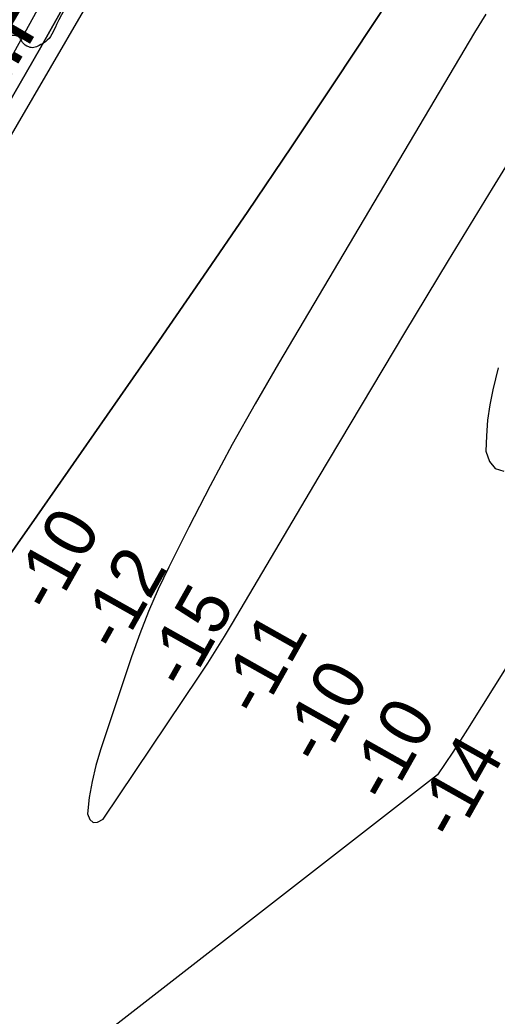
# Model space of a CAD drawing. Extents: x 3297735 to 3335592, y 670436 to 695807.
# Drawn here: x 3318736 to 3319354, y 691316 to 692609 of the extents above; entities that cross this region are included whole.
import ezdxf

# ---------------------------------------------------------------- set-up
doc = ezdxf.new("R2010")
doc.units = 0
for name, color, linetype in [('V-RIVR-EDGE', 7, 'Continuous'), ('V-RIVR-RANG', 7, 'Continuous'), ('V-TOPO-DPTH', 7, 'Continuous'), ('V-TOPO-MINR', 7, 'Continuous'), ('V-TOPO-WATR', 7, 'Continuous'), ('V-TOPO-WATR-IDEN', 7, 'Continuous')]:
    doc.layers.add(name, color=color, linetype=linetype)

msp = doc.modelspace()

# ---------------------------------------------------------------- linework, layer by layer
at = {"layer": 'V-RIVR-EDGE'}
msp.add_spline([(3319555.1, 694014.6), (3319548.5, 694002.8), (3319539.4, 693985.8), (3319509.8, 693923.3), (3319496.5, 693903), (3319479.4, 693878.2), (3319464, 693854.6), (3319445.3, 693819), (3319424.4, 693775.5), (3319406.5, 693740.7), (3319395.7, 693713), (3319386.5, 693693.1), (3319372.8, 693671.6), (3319340.3, 693621.5), (3319316.6, 693580.1), (3319295.8, 693542.9), (3319282.1, 693521), (3319271.7, 693502.3), (3319267.9, 693489.5), (3319260, 693475.8), (3319250.4, 693465.1), (3319246.2, 693454.3), (3319237.9, 693442.3), (3319231.7, 693428.7), (3319225.4, 693415), (3319219.6, 693410), (3319205.5, 693391.4), (3319185.1, 693363.3), (3319164.7, 693327.7), (3319143.1, 693301.2), (3319109.4, 693253.2), (3319083.6, 693218.5), (3319061.1, 693187.8), (3319039.5, 693157.6), (3319018.3, 693123.3), (3318994.6, 693091), (3318949.7, 693031.9), (3318931.4, 693004.6), (3318913.1, 692981.4), (3318902.3, 692962.8), (3318892.7, 692944.5), (3318876, 692916.4), (3318861.9, 692887.8), (3318841.5, 692848.5), (3318822.3, 692807.5), (3318806.5, 692774.4), (3318803.1, 692758.7), (3318804.3, 692745), (3318808, 692734.6), (3318808.8, 692730.5), (3318817.1, 692725.5), (3318826.6, 692719.2), (3318832.8, 692713), (3318835.7, 692705.5), (3318835.3, 692692.3), (3318829.9, 692681.5), (3318819.9, 692669.1), (3318809.5, 692651.3), (3318783.2, 692602.9), (3318768.7, 692580.5), (3318760.8, 692576), (3318753.7, 692573.1), (3318747.1, 692573.9), (3318739.2, 692579.8), (3318735.5, 692585.6), (3318730.6, 692588.5), (3318721.4, 692588.1), (3318700.3, 692573.6), (3318679.5, 692549.7), (3318660.8, 692522.3), (3318646.6, 692493.4), (3318637, 692477.6), (3318625, 692456.9), (3318607.1, 692434.2), (3318600, 692413.5), (3318583.3, 692372.5), (3318565.8, 692342.3), (3318547.1, 692313.7), (3318534.2, 692295.5), (3318512.6, 692258.7), (3318488, 692224.8), (3318446.4, 692155.2), (3318418.1, 692112.6), (3318397.3, 692084.5), (3318386.9, 692066.7), (3318376.5, 692048), (3318354.4, 692011.2), (3318333.2, 691976.5), (3318316.1, 691940), (3318301.6, 691917.7), (3318275.4, 691885), (3318265.8, 691873), (3318250.8, 691844.8), (3318236.6, 691808.4), (3318222.1, 691781.1), (3318195, 691714), (3318180, 691684.2), (3318162.1, 691654.8), (3318140.8, 691619.6), (3318130.4, 691603.9), (3318120.9, 691595.2), (3318105.1, 691577.9), (3318090.1, 691558.4), (3318067.7, 691532.4), (3318043.6, 691501.8), (3318020.3, 691465.8), (3317998.2, 691433.1), (3317973.7, 691392.9), (3317962.4, 691371.8), (3317929.9, 691315.1), (3317907.9, 691282.4), (3317889.2, 691263.4), (3317870.5, 691238.2), (3317844.7, 691203), (3317833.1, 691186), (3317808.1, 691148.8), (3317780.6, 691109.5), (3317756.1, 691076.4), (3317732, 691045.3), (3317684.6, 690978.7), (3317668.8, 690954.7), (3317646.3, 690922), (3317635.5, 690907.1), (3317629.2, 690900.5), (3317620.1, 690889.4), (3317608.5, 690874.5), (3317601.4, 690867), (3317592.7, 690860.4), (3317585.6, 690845.9), (3317576.9, 690836), (3317565.6, 690821.1), (3317549.4, 690801.3), (3317522.4, 690767.7), (3317502.4, 690745), (3317490, 690727.6), (3317482.5, 690713.5), (3317479.5, 690701.1), (3317475.8, 690689.9), (3317474.9, 690683.3), (3317467.9, 690674.2), (3317451.7, 690653.9), (3317427.5, 690622.9), (3317406.3, 690594), (3317381.8, 690564.6), (3317328.2, 690504.6), (3317308.2, 690483.1), (3317290.8, 690466.2), (3317272.5, 690446.3), (3317248.8, 690422.7), (3317230.9, 690402.5), (3317202.2, 690356.5), (3317170.2, 690314.3), (3317129.5, 690266.4), (3317099.1, 690227.5), (3317085.8, 690212.6), (3317074.2, 690204.3), (3317063.4, 690189.8), (3317045.1, 690163.8), (3317020.9, 690128.6), (3316996.8, 690093.9), (3316970.6, 690059.1), (3316927, 690008.2), (3316891.7, 689970.6), (3316861.7, 689930.1), (3316828, 689887.9), (3316809.3, 689860.1), (3316797.2, 689841.9), (3316783.5, 689825.4), (3316737.4, 689762.1), (3316714.9, 689729), (3316681.6, 689687.6), (3316661.7, 689665.7), (3316648, 689646.7), (3316619.7, 689606.1), (3316602.6, 689581.3), (3316583.5, 689551.9), (3316563.9, 689519.6), (3316547.7, 689499.3), (3316541.9, 689491.9), (3316538.6, 689488.6), (3316532.3, 689474.1), (3316523.2, 689461.3), (3316509, 689445.1), (3316500.3, 689431.5), (3316493.2, 689419.9), (3316485.7, 689407.9), (3316486.1, 689397.1), (3316486.5, 689375.6), (3316487.3, 689371), (3316491.4, 689370.2), (3316493.5, 689366.4), (3316494.3, 689352.8), (3316496.8, 689341.6), (3316502.5, 689336.6), (3316504.2, 689334.1), (3316504.2, 689328.7), (3316501.3, 689325.8), (3316488.8, 689321.3), (3316487.2, 689319.6), (3316487.2, 689316.7), (3316493, 689316.7), (3316502.1, 689318.3), (3316508.3, 689318.3), (3316513.3, 689315), (3316516.6, 689315), (3316524.9, 689314.5), (3316535.6, 689303.3), (3316544.7, 689293.4), (3316545.5, 689290), (3316543.5, 689288), (3316525.7, 689296.7), (3316509.9, 689304.2), (3316502.1, 689307.1), (3316490.5, 689308.4), (3316482.6, 689308), (3316478, 689308), (3316473.5, 689311.8), (3316449.5, 689323.9), (3316424.6, 689324.7), (3316401.8, 689323.1), (3316381.5, 689318.2), (3316366.5, 689316.2), (3316352.9, 689311.2), (3316334.2, 689295.5), (3316302.2, 689277.8), (3316275.2, 689257.1), (3316266.5, 689249.3), (3316249, 689224), (3316230.3, 689191.8), (3316217.8, 689162.8), (3316200.7, 689125.9), (3316182.4, 689092.8), (3316162.8, 689054.7), (3316141.2, 689024.9), (3316114.6, 688996.4), (3316081.8, 688971.6), (3316036.9, 688926.1), (3316007.4, 688897.6), (3315987, 688880.7), (3315970, 688865.8), (3315959.6, 688858.8), (3315957.1, 688852.1), (3315955.5, 688848.4), (3315953.9, 688835.5)], degree=3, dxfattribs=at)
at = {"layer": 'V-TOPO-DPTH'}
for points in [[(3318722.4, 691914.9), (3318736.6, 691934.9), (3318750.7, 691954.9), (3318764.7, 691975), (3318916.3, 692193.1), (3318973.8, 692276.6), (3319031, 692360.3), (3319087.6, 692444.5), (3319143.8, 692528.9), (3319238.8, 692672.8)], [(3319238.8, 692672.8), (3319143.8, 692528.9), (3319087.6, 692444.5), (3319031, 692360.3), (3318973.8, 692276.6), (3318916.3, 692193.1), (3318764.7, 691975), (3318750.7, 691954.9), (3318736.6, 691934.9), (3318722.4, 691914.9)], [(3317821, 691097.6), (3318051, 691423.5), (3318070.8, 691451.8), (3318090.4, 691480.2), (3318109.8, 691508.8), (3318129, 691537.5), (3318157.4, 691580.6), (3318190.6, 691631), (3318223.6, 691681.5), (3318256.2, 691732.2), (3318288.7, 691783.1), (3318450.4, 692037.8), (3318464.2, 692059.7), (3318477.7, 692081.8), (3318491, 692103.9), (3318504.1, 692126.2), (3318673.4, 692418), (3318718, 692495.4), (3318762.3, 692573), (3318806.1, 692650.9)], [(3317821, 691097.6), (3318051, 691423.5), (3318070.8, 691451.8), (3318090.4, 691480.2), (3318109.8, 691508.8), (3318129, 691537.5), (3318157.4, 691580.6), (3318190.6, 691631), (3318223.6, 691681.5), (3318256.2, 691732.2), (3318288.7, 691783.1), (3318450.4, 692037.8), (3318464.2, 692059.7), (3318477.7, 692081.8), (3318491, 692103.9), (3318504.1, 692126.2), (3318673.4, 692418), (3318718, 692495.4), (3318762.3, 692573), (3318806.1, 692650.9)]]:
    msp.add_lwpolyline(points, dxfattribs=at)
at = {"layer": 'V-TOPO-MINR'}
for points in [[(3318877.2, 692839.4), (3318696, 692509.3), (3318657.2, 692439.4), (3318618.2, 692369.6), (3318578.7, 692300.2), (3318538.8, 692230.9), (3318473.4, 692117.9), (3318466, 692105.2), (3318458.5, 692092.6), (3318450.9, 692080.1), (3318443.2, 692067.6), (3318380.3, 691966), (3318340.9, 691902.9), (3318301.4, 691839.8), (3318261.6, 691776.9), (3318221.7, 691714.1), (3318106, 691532.9), (3318091.5, 691510.6), (3318076.8, 691488.4), (3318061.7, 691466.4), (3318046.5, 691444.5), (3317923, 691270.3)], [(3318883.1, 692733.7), (3318534.8, 692134.5), (3318516, 692102.6), (3318496.8, 692070.9), (3318477.2, 692039.5), (3318457.3, 692008.3), (3318181, 691581.5), (3318168.8, 691562.9), (3318156.5, 691544.3), (3318144.1, 691525.9), (3318131.5, 691507.4), (3318118.9, 691489.1), (3318106.2, 691470.8), (3318093.5, 691452.5), (3318080.8, 691434.2), (3317690.3, 690875.4)], [(3319238.8, 692672.8), (3319143.8, 692528.9), (3319087.6, 692444.5), (3319031, 692360.3), (3318973.8, 692276.6), (3318916.3, 692193.1), (3318764.7, 691975), (3318750.7, 691954.9), (3318736.6, 691934.9), (3318722.4, 691914.9)], [(3319339.3, 692616.7), (3319324.9, 692592.6), (3319070.7, 692163.2), (3319040.4, 692110.7), (3319010.8, 692057.9), (3318982.4, 692004.4), (3318954.6, 691950.6), (3318928.6, 691898.6), (3318915, 691870.2), (3318902.3, 691841.4), (3318890.9, 691812.1), (3318880.3, 691782.4), (3318840.1, 691661.8), (3318834.1, 691641.4), (3318829.1, 691620.7), (3318825.6, 691599.8), (3318823.1, 691578.7), (3318826.3, 691571.4), (3318830.5, 691567.3), (3318836.4, 691567.8), (3318843.4, 691571.6), (3318967.9, 691757.3), (3318979.1, 691774.3), (3318990.1, 691791.4), (3319000.7, 691808.7), (3319011.2, 691826.1), (3319122.2, 692014.5), (3319178.2, 692108.7), (3319234.4, 692202.8), (3319291.2, 692296.6), (3319348.3, 692390.1), (3319447.7, 692551.9)], [(3319355.4, 692157.6), (3319348.7, 692129), (3319344.8, 692109.3), (3319341.8, 692089.4), (3319340.2, 692069.4), (3319339.5, 692049.2), (3319344.2, 692036), (3319351.6, 692026.7), (3319363, 692023.5)], [(3319490.8, 691968.1), (3319315.9, 691688.5), (3319296.6, 691658.6), (3319276.7, 691629.1), (3318703.1, 691182.6)]]:
    msp.add_lwpolyline(points, dxfattribs=at)
at = {"layer": 'V-TOPO-WATR'}
msp.add_lwpolyline([(3318806.1, 692650.9), (3318762.3, 692573), (3318718, 692495.4), (3318673.4, 692418), (3318504.1, 692126.2), (3318491, 692103.9), (3318477.7, 692081.8), (3318464.2, 692059.7), (3318450.4, 692037.8), (3318288.7, 691783.1), (3318256.2, 691732.2), (3318223.6, 691681.5), (3318190.6, 691631), (3318157.4, 691580.6), (3318129, 691537.5), (3318109.8, 691508.8), (3318090.4, 691480.2), (3318070.8, 691451.8), (3318051, 691423.5), (3317821, 691097.6)], dxfattribs=at)

# ---------------------------------------------------------------- texts
at = {"layer": 'V-RIVR-RANG'}
for s, p in [('-10', (3318778.2, 691836.3)), ('-12', (3318864.3, 691785.4)), ('-15', (3318951.8, 691737)), ('-11', (3319046.5, 691701.3)), ('-10', (3319126.2, 691639.1)), ('-10', (3319213.2, 691589.8)), ('-14', (3319300.7, 691541.4))]:
    msp.add_text(s, height=67, rotation=60.599, dxfattribs=at).set_placement(p)
at = {"layer": 'V-TOPO-WATR-IDEN'}
msp.add_text('L.W.R.P.', height=83, rotation=59.6242, dxfattribs=at).set_placement((3318572.7, 692277.6))

doc.saveas('drawing.dxf')
